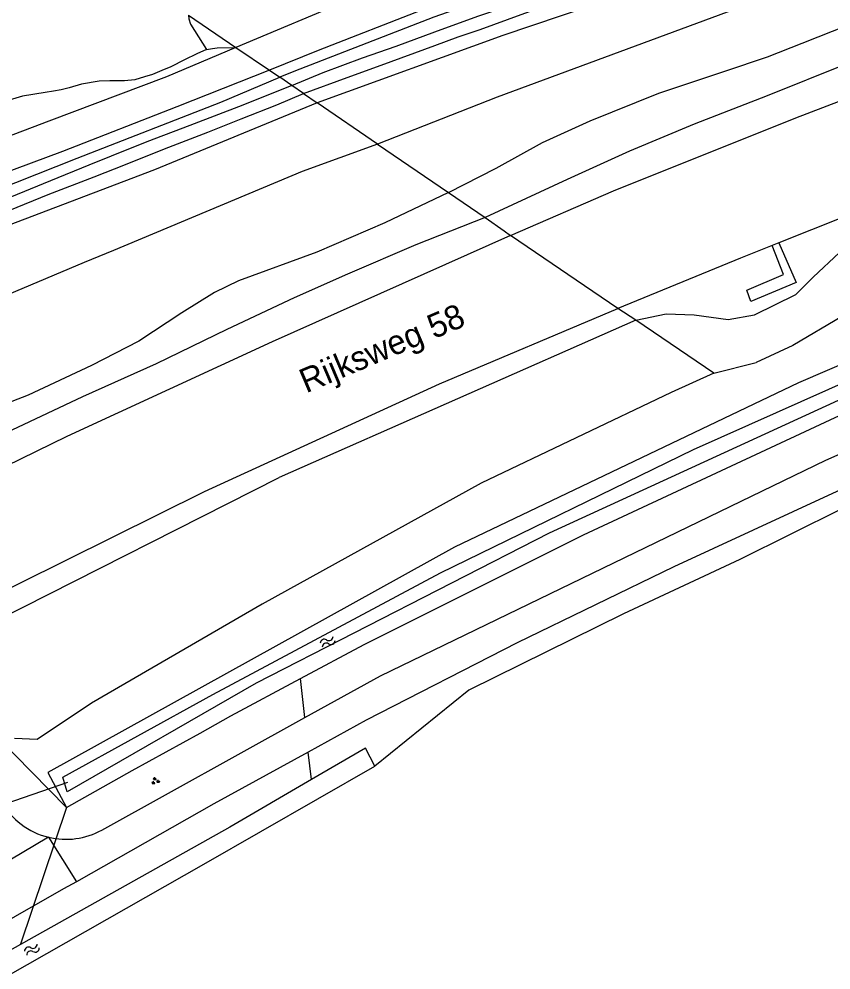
# Model space of a CAD drawing. Extents: x 135990 to 139000, y 393500 to 396000.
# Drawn here: x 136805.8 to 136889.5, y 395687.3 to 395785.4 of the extents above; entities that cross this region are included whole.
import ezdxf

# ---------------------------------------------------------------- set-up
doc = ezdxf.new("R2010")
doc.units = 0
for name, color, linetype in [('gg-afsc-faunaraster', 7, 'Continuous'), ('gg-anno-openbare ruimte label', 7, 'Continuous'), ('gg-knt-BGT kruinlijn', 7, 'Continuous'), ('gg-knt-bronhoudergrens', 7, 'Continuous'), ('gg-knt-verharding', 7, 'Continuous'), ('gg-kntw-bovenkant insteek waterloop', 7, 'Continuous'), ('gg-kntw-waterlijn', 7, 'Continuous'), ('gg-kwrk-duiker nz buis', 7, 'Continuous'), ('gt-grn-groengrens', 7, 'Continuous'), ('gt-grn-weggrens', 7, 'Continuous'), ('gt-symb-groenvak', 7, 'Continuous'), ('gt-symb-watersymbool', 7, 'Continuous'), ('gx-grn-maaiveld', 7, 'Continuous')]:
    doc.layers.add(name, color=color, linetype=linetype)

# ---------------------------------------------------------------- blocks, each defined once
blk = doc.blocks.new('gt0-WA')
at = {"layer": 'gt-symb-watersymbool'}
for centre, start, end in [((-0.323, 0.022), 28.07249, 151.92751), ((0.427, 0.422), 208.07248, 331.92751), ((-0.323, -0.428), 28.07249, 151.92751), ((0.427, -0.028), 208.07248, 331.92751)]:
    blk.add_arc(centre, 0.425, start, end, dxfattribs=at)
blk = doc.blocks.new('gt0-GRVAK')
at = {"layer": 'gt-symb-groenvak'}
for p, q in [((-0.11, 0.189), (-0.228, 0.24)), ((-0.182, 0.153), (0.088, 0.153)), ((-0.091, 0.211), (-0.156, 0.322)), ((-0.047, 0.214), (-0.047, 0.393)), ((-0.004, 0.211), (0.061, 0.322)), ((0.015, 0.189), (0.133, 0.24)), ((0.262, -0.052), (0.197, 0.059)), ((0.305, -0.049), (0.305, 0.13)), ((0.349, -0.052), (0.414, 0.059)), ((-0.245, -0.228), (-0.363, -0.177)), ((-0.318, -0.264), (-0.047, -0.264)), ((-0.226, -0.206), (-0.291, -0.095)), ((-0.183, -0.203), (-0.183, -0.024)), ((-0.139, -0.206), (-0.074, -0.095)), ((-0.12, -0.228), (-0.002, -0.177)), ((0.243, -0.074), (0.125, -0.023)), ((0.17, -0.11), (0.441, -0.11)), ((0.368, -0.074), (0.486, -0.023))]:
    blk.add_line(p, q, dxfattribs=at)

msp = doc.modelspace()

# ---------------------------------------------------------------- linework, layer by layer
at = {"layer": 'gg-afsc-faunaraster'}
msp.add_line((136803.226, 395711.711), (136810.73, 395704.091), dxfattribs=at)
msp.add_lwpolyline([(136810.73, 395704.091), (136817.474, 395707.911), (136824.486, 395711.769), (136827.645, 395713.532)], dxfattribs=at)
at = {"layer": 'gg-knt-BGT kruinlijn'}
for p, q in [((136887.652, 395758.759), (136890.34, 395761.304)), ((136885.864, 395756.969), (136887.652, 395758.759)), ((136881.578, 395754.866), (136885.864, 395756.969)), ((136869.374, 395754.328), (136832.637, 395738.111)), ((136869.374, 395754.328), (136872.503, 395754.966)), ((136872.503, 395754.966), (136875.364, 395754.885)), ((136875.364, 395754.885), (136878.896, 395754.405)), ((136878.896, 395754.405), (136881.578, 395754.866)), ((136799.121, 395721.128), (136832.637, 395738.111))]:
    msp.add_line(p, q, dxfattribs=at)
for points in [[(136999.535, 395814.895), (136991.548, 395812.912), (136984.167, 395810.891), (136975.78, 395808.457), (136967.414, 395805.931), (136962.983, 395804.487), (136957.237, 395802.678), (136949.78, 395800.441), (136943.263, 395798.557), (136935.638, 395796.16), (136927.91, 395793.699), (136919.415, 395790.834), (136911.506, 395788.064), (136906.868, 395786.469), (136900.661, 395784.152), (136896.872, 395782.866), (136891.096, 395780.747), (136882.882, 395777.445), (136875.389, 395774.521), (136868.719, 395771.741), (136862.288, 395768.805), (136853.84, 395764.91)], [(136853.84, 395764.91), (136846.722, 395762.074), (136839.658, 395759.072), (136834.156, 395756.641), (136827.228, 395753.354), (136819.943, 395749.838), (136812.38, 395746.414), (136805.087, 395743.002), (136797.885, 395739.575), (136791.937, 395736.506), (136788.875, 395734.723)]]:
    msp.add_lwpolyline(points, dxfattribs=at)
at = {"layer": 'gg-knt-bronhoudergrens'}
msp.add_line((136808.862, 395701.028), (136797.191, 395694.088), dxfattribs=at)
at = {"layer": 'gg-knt-verharding'}
msp.add_line((136814.36, 395701.77), (136835.263, 395713.362), dxfattribs=at)
for points in [[(136835.263, 395713.362), (136843.05, 395717.68), (136888.95, 395739.9), (136925.21, 395756.02), (136967.69, 395771.86), (137000, 395781.813)], [(137002.329, 395778.811), (136990.637, 395775.422), (136973.513, 395770.016), (136956.998, 395764.404), (136940.836, 395758.434), (136924.369, 395751.89), (136905.741, 395743.749), (136889.632, 395736.464), (136873.271, 395728.886), (136857.151, 395721.082), (136841.573, 395713.082), (136835.604, 395709.811)], [(136835.604, 395709.811), (136825.887, 395704.485), (136811.741, 395696.447)], [(136811.741, 395696.447), (136810.424, 395695.698), (136795.197, 395687.033), (136774.799, 395674.937), (136759.213, 395665.03), (136757.373, 395663.827)]]:
    msp.add_lwpolyline(points, dxfattribs=at)
for centre, radius, start, end in [((136810.663, 395708.445), 7.632, 209.37357, 256.35171), ((136810.66, 395708.447), 7.633, 256.37732, 298.99487)]:
    msp.add_arc(centre, radius, start, end, dxfattribs=at)
at = {"layer": 'gg-kntw-bovenkant insteek waterloop'}
for p, q in [((136827.645, 395713.532), (136834.837, 395717.385)), ((136808.8, 395707.7), (136810.73, 395704.091))]:
    msp.add_line(p, q, dxfattribs=at)
for points in [[(137000, 395789.345), (136965.67, 395778.84), (136925.97, 395765.022), (136886.13, 395747.881), (136850.68, 395730.911), (136808.8, 395707.7)], [(136834.837, 395717.385), (136841.4, 395720.901), (136863.987, 395732.203), (136892.395, 395745.472), (136923.92, 395758.491), (136940.431, 395764.845), (136960.753, 395771.976), (136974.932, 395776.454), (137000, 395783.817)], [(136842.473, 395708.352), (136841.526, 395710.224), (136835.96, 395706.982)], [(136774.205, 395669.691), (136802.703, 395685.658), (136824.854, 395698.248), (136842.473, 395708.352)], [(136835.96, 395706.982), (136827.533, 395702.073), (136789.229, 395680.607), (136778.691, 395674.751), (136772.689, 395671.151), (136774.205, 395669.691)]]:
    msp.add_lwpolyline(points, dxfattribs=at)
at = {"layer": 'gg-kntw-waterlijn'}
for points in [[(136810.336, 395707.218), (136825.808, 395715.736), (136849.259, 395728.294), (136875.298, 395740.998), (136911.742, 395757.242), (136931.28, 395764.821), (136954.278, 395772.88), (136968.737, 395777.398), (136994.091, 395785.32)], [(136993.792, 395783.757), (136971.502, 395777.034), (136924.446, 395760.782), (136910.88, 395755.318), (136892.315, 395747.011), (136860.433, 395732.386), (136830.272, 395716.909), (136810.785, 395705.699), (136810.336, 395707.218)]]:
    msp.add_lwpolyline(points, dxfattribs=at)
at = {"layer": 'gg-kwrk-duiker nz buis'}
for p, q in [((136791.902, 395700.119), (136810.857, 395706.712)), ((136810.73, 395704.091), (136805.975, 395689.992))]:
    msp.add_line(p, q, dxfattribs=at)
at = {"layer": 'gt-grn-groengrens'}
for p, q in [((136835.263, 395713.362), (136834.837, 395717.385)), ((136835.96, 395706.982), (136835.604, 395709.811))]:
    msp.add_line(p, q, dxfattribs=at)
msp.add_lwpolyline([(136962.316, 395764.268), (136961.33, 395763.927), (136944.607, 395757.921), (136933.675, 395753.654), (136922.635, 395749.225), (136913.03, 395744.859), (136901.89, 395739.685), (136890.587, 395734.883), (136880.083, 395729.66), (136868.092, 395724.055), (136852.178, 395716.193), (136842.473, 395708.352)], dxfattribs=at)
at = {"layer": 'gt-grn-weggrens'}
msp.add_line((136808.862, 395701.028), (136811.741, 395696.447), dxfattribs=at)
at = {"layer": 'gx-grn-maaiveld'}
for p, q in [((136840.297, 395787.532), (136828.18, 395782.43)), ((136823.302, 395785.774), (136828.18, 395782.43)), ((136828.18, 395782.43), (136831.617, 395780.085)), ((136831.617, 395780.085), (136832.68, 395779.36)), ((136833.935, 395778.504), (136832.68, 395779.36)), ((136835.142, 395777.68), (136833.935, 395778.504)), ((136835.142, 395777.68), (136836.551, 395776.715)), ((136842.769, 395772.478), (136836.551, 395776.715)), ((136842.769, 395772.478), (136850.076, 395767.492)), ((136850.076, 395767.492), (136853.84, 395764.91)), ((136867.504, 395755.527), (136856.46, 395763.055)), ((136884.097, 395762.293), (136883.412, 395762.02)), ((136869.374, 395754.328), (136867.504, 395755.527)), ((136877.401, 395748.851), (136869.374, 395754.328)), ((136890.674, 395754.719), (136885.548, 395751.725)), ((136885.548, 395751.725), (136881.761, 395749.958)), ((136877.401, 395748.851), (136881.761, 395749.958)), ((136877.401, 395748.851), (136873.02, 395746.872)), ((136873.02, 395746.872), (136853.443, 395737.515)), ((136853.443, 395737.515), (136830.877, 395725.067)), ((136830.877, 395725.067), (136813.312, 395714.862)), ((136813.312, 395714.862), (136807.708, 395711.111)), ((136807.708, 395711.111), (136805.377, 395711.203))]:
    msp.add_line(p, q, dxfattribs=at)
for points in [[(137100.652, 395846.776), (137090.213, 395845.613), (137074.59, 395843.372), (137060.481, 395841.521), (137047.371, 395839.342), (137032.041, 395836.53), (137015.133, 395833.526), (136998.564, 395829.973), (136986.261, 395826.994), (136976.269, 395824.788), (136964.738, 395821.753), (136953.414, 395818.683), (136939.886, 395815.095), (136926.962, 395811.336), (136914.395, 395807.565), (136899.138, 395802.66), (136887.275, 395798.857), (136873.467, 395794.094), (136859.706, 395789.521), (136848.551, 395785.551), (136834.123, 395779.97), (136832.68, 395779.36)], [(136856.46, 395763.055), (136867.071, 395767.65), (136885.862, 395775.183), (136905.932, 395782.86), (136924.107, 395789.337), (136943.244, 395795.551), (136965.014, 395802.241), (136986.439, 395808.267), (137007.631, 395813.726), (137023.9, 395817.584), (137044.37, 395821.985), (137064.339, 395825.845), (137083.894, 395829.271), (137090.054, 395830.21)], [(137042.612, 395829.731), (137031.556, 395827.611), (137018.626, 395825.167), (136989.51, 395818.229), (136982.517, 395816.521), (136966.318, 395812.074), (136946.833, 395807.159), (136936.995, 395804.532), (136919.441, 395799.972), (136902.013, 395794.193), (136883.5, 395787.861), (136855.068, 395777.304), (136842.769, 395772.478)], [(136988.306, 395828.559), (136983.011, 395827.258), (136976.492, 395825.675), (136967.118, 395823.178), (136960.011, 395821.273), (136952.758, 395819.3), (136943.231, 395816.784), (136938.406, 395815.349), (136927.368, 395812.235), (136918.197, 395809.539), (136909.531, 395806.942), (136901.937, 395804.704), (136896.066, 395802.916), (136888.026, 395800.283), (136879.581, 395797.556), (136869.578, 395794.171), (136857.842, 395790.208), (136847.381, 395786.317), (136836.638, 395782.104), (136831.617, 395780.085)], [(137082.255, 395818.02), (137068.627, 395815.426), (137048.481, 395811.366), (137024.83, 395806.448), (137007.661, 395802.234), (136983.455, 395795.946), (136962.676, 395790.005), (136944.089, 395784.242), (136925.12, 395777.84), (136908.852, 395772.025), (136894.015, 395766.255), (136884.097, 395762.293)], [(136931.386, 395807.994), (136915.449, 395803.453), (136899.514, 395798.331), (136880.592, 395792.088), (136867.688, 395787.741), (136855.653, 395783.657), (136836.551, 395776.715)], [(136833.935, 395778.504), (136837.167, 395779.855), (136841.218, 395781.371), (136844.684, 395782.554), (136848.661, 395784.036), (136853.097, 395785.65), (136856.847, 395786.894), (136860.02, 395787.99), (136861.469, 395788.478), (136863.392, 395789.172), (136865.873, 395790.061), (136868.763, 395791.035), (136873.184, 395792.569), (136876.436, 395793.662), (136880.663, 395795.15), (136884.775, 395796.586), (136889.605, 395798.235)], [(136835.142, 395777.68), (136839.644, 395779.329), (136842.767, 395780.47), (136846.603, 395781.863), (136848.68, 395782.626), (136851.053, 395783.512), (136853.316, 395784.288), (136857.554, 395785.839), (136864.771, 395788.438), (136872.491, 395791.142), (136876.237, 395792.437), (136877.832, 395792.966), (136880.522, 395793.89), (136881.574, 395794.267), (136887.08, 395796.184), (136892.476, 395797.857)], [(136823.302, 395785.774), (136823.317, 395785.38), (136823.502, 395784.816), (136825.146, 395782.21)], [(136850.076, 395767.492), (136854.967, 395769.974), (136859.768, 395772.632), (136864.656, 395774.864), (136871.751, 395777.73), (136878.539, 395779.995), (136882.92, 395781.457), (136886.514, 395782.869), (136891.287, 395784.76)], [(136828.18, 395782.43), (136821.023, 395779.408), (136808.899, 395774.842), (136800.728, 395771.732)], [(136825.146, 395782.21), (136824.138, 395781.783), (136822.885, 395781.156), (136821.471, 395780.44), (136820.529, 395780.043), (136819.577, 395779.656), (136818.749, 395779.39), (136817.756, 395779.092), (136816.702, 395778.988), (136815.766, 395778.978), (136815.201, 395778.993), (136814.101, 395778.958), (136812.282, 395778.633), (136810.989, 395778.26), (136810.178, 395778.047), (136809.379, 395777.923), (136808.519, 395777.785), (136806.183, 395777.403), (136803.498, 395776.61), (136801.228, 395775.901)], [(136825.146, 395782.21), (136825.753, 395782.337), (136826.243, 395782.394), (136828.18, 395782.43)], [(136831.617, 395780.085), (136822.099, 395776.324), (136810.307, 395771.708), (136802.055, 395768.661)], [(136788.386, 395754.257), (136787.99, 395754.283), (136787.709, 395754.424), (136787.417, 395754.744), (136787.183, 395755.107), (136787.088, 395755.368), (136787.075, 395755.653), (136787.101, 395756.079), (136787.439, 395756.685), (136789.091, 395758.869), (136791.585, 395761.471), (136793.04, 395762.595), (136795.17, 395763.874), (136801.325, 395766.862), (136811.815, 395771.035), (136826.605, 395776.789), (136832.68, 395779.36)], [(136833.935, 395778.504), (136828.9, 395776.495), (136823.41, 395774.371), (136819.003, 395772.693), (136815.334, 395771.225), (136813.038, 395770.292), (136809.072, 395768.676), (136804.303, 395766.742), (136799.661, 395764.818), (136797.927, 395764.006), (136796.44, 395763.262), (136795.118, 395762.482), (136793.686, 395761.451), (136791.441, 395759.572), (136790.214, 395758.359), (136789.963, 395758.111), (136789.06, 395757.067), (136788.657, 395756.579)], [(136804.872, 395765.665), (136808.835, 395767.26), (136813.571, 395769.089), (136816.807, 395770.355), (136820.82, 395771.995), (136825.263, 395773.69), (136828.714, 395775.058), (136832.38, 395776.521), (136835.142, 395777.68)], [(136836.551, 395776.715), (136819.794, 395769.806), (136803.239, 395763.515), (136798.171, 395761.459), (136796.643, 395760.713), (136795.875, 395760.269), (136794.874, 395759.638), (136789.665, 395755.135), (136788.797, 395754.454), (136788.386, 395754.257)], [(136842.769, 395772.478), (136835.005, 395769.658), (136815.55, 395761.507), (136812.527, 395760.266), (136799.89, 395754.931), (136786.468, 395748.502)], [(136850.076, 395767.492), (136843.515, 395764.344), (136836.512, 395761.319), (136828.43, 395758.39), (136825.956, 395757.191), (136822.607, 395755.09), (136818.156, 395752.155), (136813.313, 395749.659), (136806.789, 395746.583), (136799.723, 395743.884), (136796.744, 395742.647), (136794.028, 395742.188), (136792.386, 395742.357), (136791.12, 395742.98), (136789.588, 395744.098), (136788.155, 395745.582), (136786.988, 395747.304), (136786.468, 395748.502)], [(136853.84, 395764.91), (136855.81, 395763.515), (136856.46, 395763.055)], [(136856.46, 395763.055), (136831.894, 395752.096), (136810.748, 395742.339), (136790.228, 395732.289), (136789.708, 395733.286)], [(136884.097, 395762.293), (136885.888, 395758.194), (136881.228, 395756.263), (136880.803, 395757.415), (136884.569, 395759.041), (136883.412, 395762.02)], [(136883.412, 395762.02), (136880.144, 395760.714), (136867.504, 395755.527)], [(136796.246, 395721.496), (136801.463, 395724.232), (136801.179, 395724.876), (136824.943, 395736.665), (136849.132, 395747.759), (136867.504, 395755.527)]]:
    msp.add_lwpolyline(points, dxfattribs=at)

# ---------------------------------------------------------------- block references
at = {"layer": 'gt-symb-groenvak'}
msp.add_blockref('gt0-GRVAK', (136819.868, 395706.819), dxfattribs=at)
at = {"layer": 'gt-symb-watersymbool'}
for p, rotation in [((136837.574, 395721.144), 27.76921269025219), ((136807.112, 395689.42), 29.616909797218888)]:
    msp.add_blockref('gt0-WA', p, dxfattribs=dict(at, rotation=rotation))

# ---------------------------------------------------------------- texts
at = {"layer": 'gg-anno-openbare ruimte label'}
msp.add_text('Rijksweg 58', height=2.5, rotation=23, dxfattribs=at).set_placement((136835.4, 395746.769))

doc.saveas('drawing.dxf')
